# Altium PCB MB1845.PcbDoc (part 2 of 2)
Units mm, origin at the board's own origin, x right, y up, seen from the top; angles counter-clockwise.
Board outline 43.1 x 47.12 mm, 4 copper layers (Top Layer, Internal 1, Internal 2, Bottom Layer), stack 1.565 mm thick; 96 components, 86 nets, 349 pads, 596 vias.
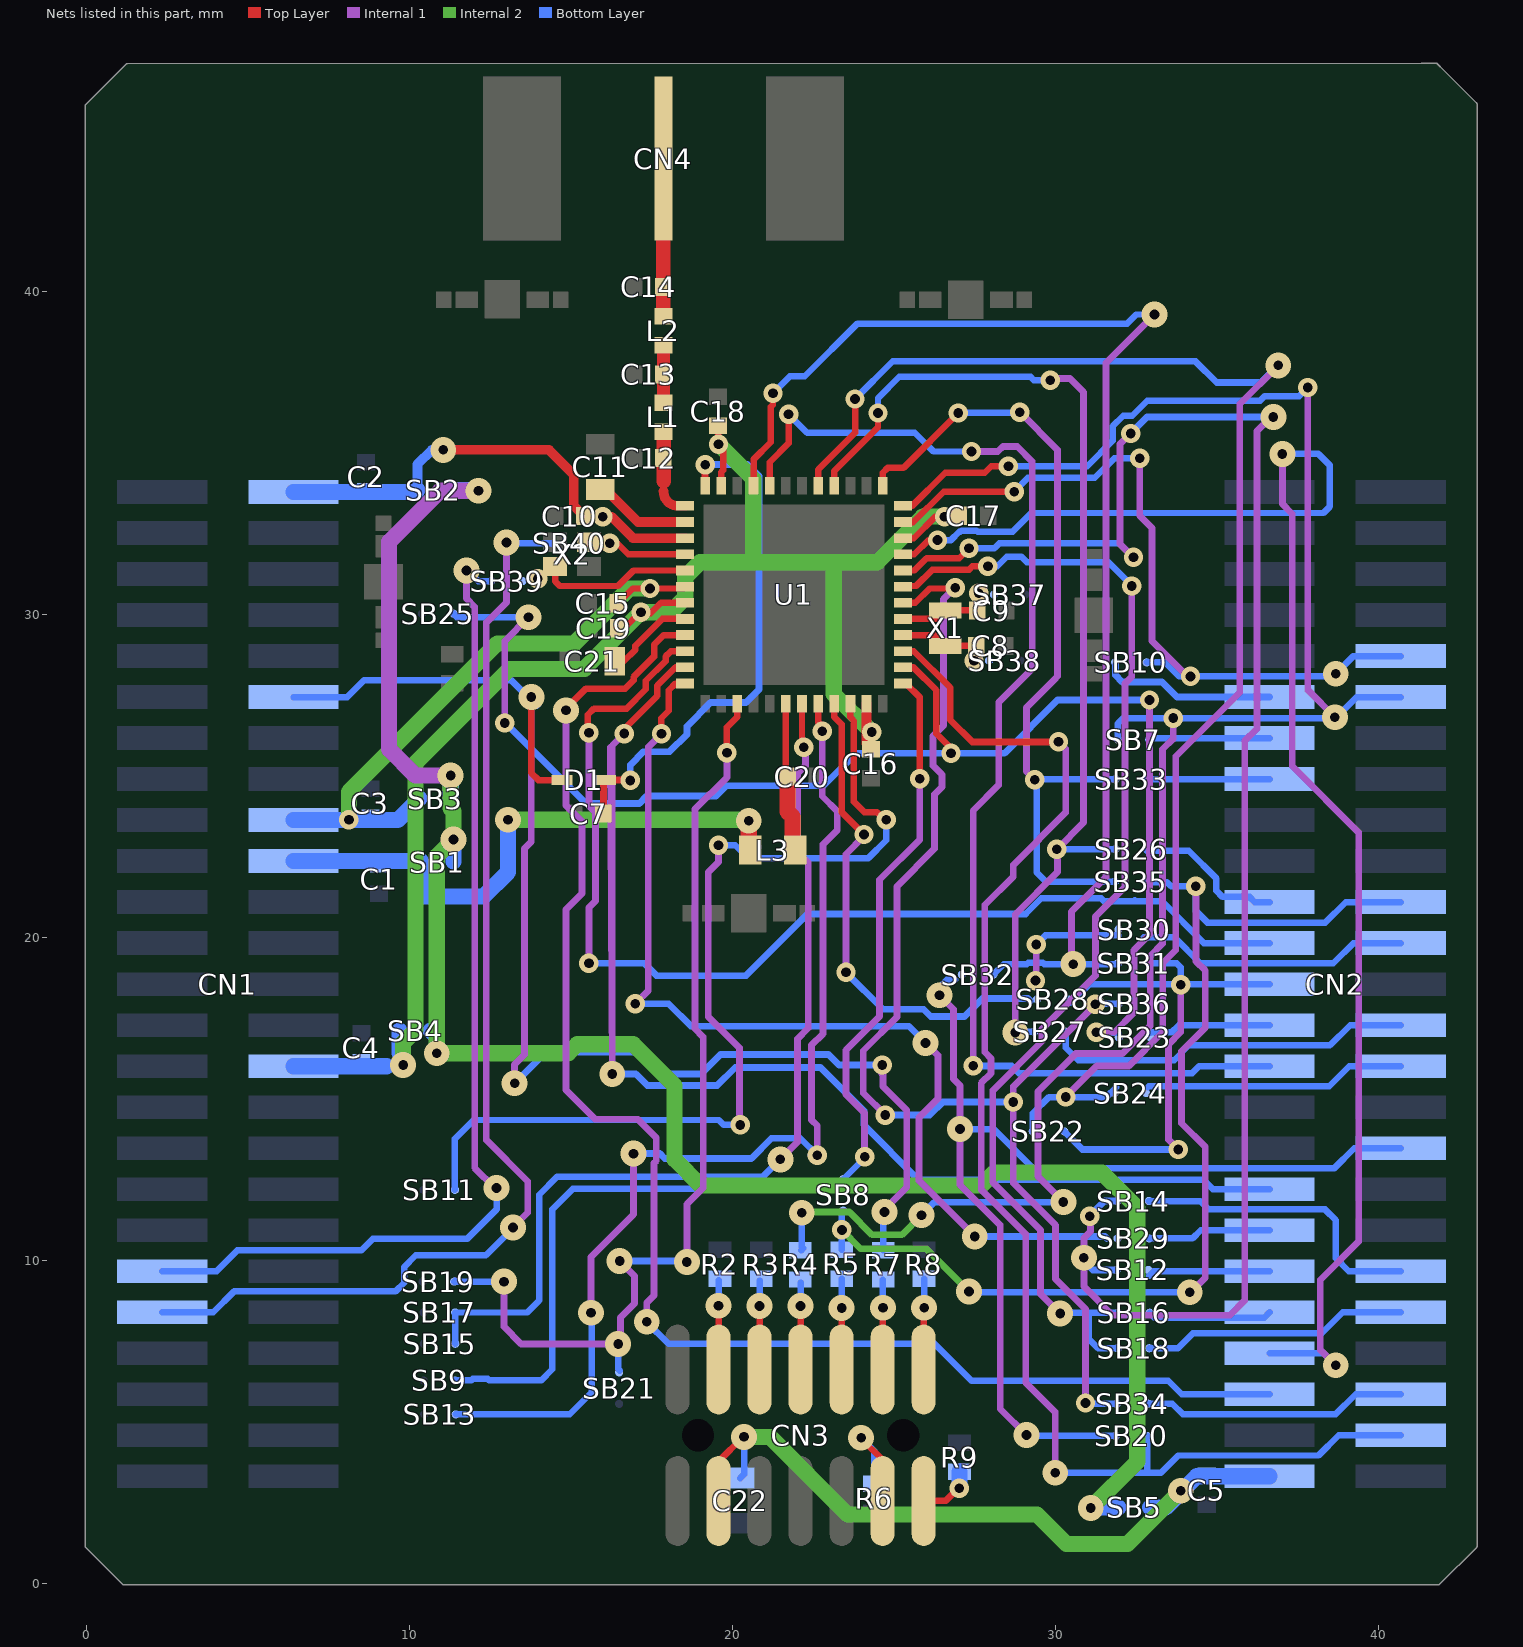
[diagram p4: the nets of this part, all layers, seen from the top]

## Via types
v1: diameter 0.6, hole 0.3, Top Layer to Bottom Layer, tented both sides, 513 vias
v2: diameter 0.8, hole 0.3, Top Layer to Bottom Layer, tented both sides, 83 vias

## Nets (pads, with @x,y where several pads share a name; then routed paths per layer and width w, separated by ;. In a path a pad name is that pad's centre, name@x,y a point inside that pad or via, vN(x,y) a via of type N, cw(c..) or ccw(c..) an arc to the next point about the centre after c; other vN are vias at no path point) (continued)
GPIO30: CN2.10 SB10.1 U1.23 | length 24.4
  Top Layer w0.2: U1.23@25.27,32.858 25.591,32.858 26.531,33.798 v1(28.715,33.798)
  Internal 1 w0.21: v1(32.601,34.835) 32.601,33.055 32.982,32.674 32.982,29.175 34.036,28.122 34.149,28.235 34.174,28.21 v1(34.174,28.077)
  Bottom Layer w0.2: v1(28.715,33.798) 29.143,34.225 31.21,34.225 31.82,34.835 v1(32.601,34.835) ; SB10.1@32.826,28.514 33.388,28.514 33.824,28.077 v1(34.174,28.077) ; 33.824,28.083 38.596,28.083 v2(38.672,28.159) 39.221,28.708 CN2.10@40.688,28.708
GPIO31: CN2.11 SB10.2 | length 5.4
  Bottom Layer w0.21: SB10.2@31.851,28.423 31.851,28.117 32.059,27.909 33.289,27.909 33.76,27.438 CN2.11@36.624,27.438
GPIO32: CN2.12 R4.2 SB7.1 U1.24 | length 62.3
  Top Layer w0.2: U1.24@25.27,33.358 25.553,33.358 26.581,34.386 27.804,34.386 28.004,34.585 v1(28.537,34.585)
  Internal 1 w0.21: v2(30.239,11.802) 29.452,12.589 29.452,15.227 30.624,16.399 32.068,16.399 32.931,17.263 32.931,19.422 33.312,19.803 33.312,25.822 33.643,26.153 v1(33.643,26.788) ; v1(37.808,37.024) 37.808,27.651 v2(38.646,26.813)
  Internal 2 w0.21: v2(22.136,11.471) 22.195,11.471 22.216,11.493 23.611,11.493 24.318,10.786 25.235,10.786 v2(25.845,11.395)
  Bottom Layer w0.2: R4.2@22.118,10.302 22.187,10.372 22.136,10.423 v2(22.136,11.471) ; v2(25.845,11.395) 26.251,11.802 v2(30.239,11.802) ; v1(28.537,34.585) 30.976,34.585 31.772,35.382 31.772,35.829 32.094,36.151 32.37,36.151 32.836,36.617 36.33,36.617 36.472,36.759 37.544,36.759 v1(37.808,37.024) ; SB7.1@31.922,26.2 31.922,26.617 32.093,26.788 v1(33.643,26.788) 38.672,26.788 39.323,27.438 CN2.12@40.688,27.438
GPIO33: CN2.13 SB7.2 | length 3.7
  Bottom Layer w0.2: SB7.2@32.897,26.2 32.929,26.168 CN2.13@36.624,26.168
GPIO34: CN2.15 SB33.1 | length 3.8
  Bottom Layer w0.2: SB33.1@32.844,24.832 32.91,24.898 CN2.15@36.624,24.898
GPIO37: CN2.21 SB26.1 | length 4.7
  Bottom Layer w0.2: SB26.1@32.824,22.679 34.119,22.679 34.977,21.821 34.977,21.44 35.167,21.25 36.005,21.25 36.167,21.088 CN2.21@36.624,21.088
GPIO38: CN2.22 R5.2 SB8.1 SB35.1 | length 35.3
  Internal 1 w0.21: v2(34.151,9.008) 34.176,9.008 34.633,9.465 34.633,13.505 33.897,14.242 33.897,16.47 34.633,17.207 34.633,18.964 34.343,19.255 v1(34.343,21.581)
  Internal 2 w0.21: v1(23.381,10.938) 23.965,10.354 25.997,10.354 v2(27.318,9.033)
  Bottom Layer w0.2: R5.2@23.376,10.328 23.376,11.402 ; v2(27.318,9.033) v2@27.343,9.008 ; SB35.1@32.829,21.708 33.448,21.708 33.575,21.581 v1(34.343,21.581) 34.343,20.813 34.701,20.454 38.351,20.454 38.985,21.088 CN2.22@40.688,21.088
  Bottom Layer w0.21: v2@27.343,9.008 v2(34.151,9.008)
GPIO39: CN2.23 U1.46 | length 34.8
  Top Layer w0.2: v1(15.547,26.33) 15.547,26.338 15.514,26.305 15.514,26.89 15.705,27.081 16.715,27.081 17.31,27.677 17.31,27.941 17.92,28.55 17.92,28.693 18.086,28.858 U1.46@18.52,28.858
  Internal 1 w0.21: v1@15.547,19.197 15.547,20.92 15.749,21.122 15.749,23.86 15.547,24.062 v1(15.547,26.33)
  Bottom Layer w0.2: 29.071,20.726 29.551,21.206 31.405,21.206 31.489,21.123 32.433,21.123 32.455,21.144 32.476,21.123 33.246,21.123 33.267,21.144 34.592,19.818 CN2.23@36.624,19.818
  Bottom Layer w0.21: v1(15.547,19.193) 17.262,19.193 17.643,18.812 20.409,18.812 22.314,20.717 29.071,20.717
GPIO40: CN2.24 SB30.2 | length 8.6
  Bottom Layer w0.2: 32.733,20.006 33.668,20.006 34.481,19.193 38.596,19.193 39.221,19.818 CN2.24@40.688,19.818
GPIO41: CN2.25 SB22.1 SB28.2 SB31.2 | length 17.1
  Internal 1 w0.21: v1(33.795,13.427) 33.49,13.732 33.49,16.678 33.871,17.059 v1(33.871,18.533)
  Bottom Layer w0.2: 30.472,17.974 31.047,18.548 v1@33.871,18.548 ; SB31.2@32.911,19.193 33.745,19.193 33.871,19.066 v1@33.871,18.548 ; CN2.25@36.624,18.548 v1@33.871,18.548
  Bottom Layer w0.21: SB22.1@30.266,13.988 30.827,13.427 v1(33.795,13.427)
GPIO42: CN2.27 SB23.2 SB36.2 | length 4.5
  Bottom Layer w0.2: 32.921,17.278 SB36.2@32.921,17.941 ; 32.93,17.044 32.921,17.053 33.585,17.053 33.811,17.278 CN2.27@36.624,17.278
GPIO43: CN2.28 SB27.1 | length 11.5
  Bottom Layer w0.2: SB27.1@30.31,17.075 30.31,16.582 30.696,16.196 33.668,16.196 34.125,16.653 38.494,16.653 39.119,17.278 CN2.28@40.688,17.278
GPIO44: CN2.29 U1.32 | length 39.6
  Top Layer w0.2: U1.32@21.145,33.983 21.145,34.711 21.73,35.297 v1(21.73,36.198)
  Internal 1 w0.21: v1(27.394,35.043) 28.207,35.043 28.366,35.201 28.81,35.201 29.274,34.738 29.274,28.313 28.237,27.276 28.237,24.709 27.445,23.917 v1(27.445,16.018)
  Bottom Layer w0.2: v1(21.73,36.198) 22.302,35.627 25.633,35.627 26.217,35.043 v1(27.394,35.043)
  Bottom Layer w0.21: v1(27.445,16.018) 28.639,16.018 28.867,15.789 34.227,15.789 34.446,16.008 CN2.29@36.624,16.008
GPIO45: CN2.30 SB24.1 | length 8.1
  Bottom Layer w0.2: 32.851,15.354 32.88,15.383 33.708,15.383 33.713,15.388 34.252,15.388 34.257,15.383 38.469,15.383 39.094,16.008 CN2.30@40.688,16.008
GPIO46: CN2.34 SB20.2 SB32.2 | length 32.9
  Internal 1 w0.21: v2(26.404,18.202) 26.835,17.771 26.835,15.612 27.039,15.408 v2(27.039,14.062) 27.039,12.334 28.283,11.089 28.283,5.401 v2(29.096,4.588)
  Internal 2 w0.21: v2(29.096,4.588) v2@29.147,4.588
  Bottom Layer w0.2: v2@26.412,18.21 v2(26.404,18.202) 26.404,18.456 26.632,18.685 26.894,18.685 ; v2@27.039,14.163 v2(27.039,14.062) 28.086,14.062 29.305,12.843 38.621,12.843 39.246,13.468 CN2.34@40.688,13.468 ; v2@29.096,4.557 SB20.2@31.858,4.557
GPIO47: CN2.35 U1.47 | length 46.4
  Top Layer w0.2: v1(16.644,26.308) 16.572,26.379 17.183,26.991 17.666,27.473 17.666,27.793 18.231,28.358 U1.47@18.52,28.358
  Internal 1 w0.21: 16.218,25.882 v2(16.269,15.764) 16.269,25.933 v1(16.644,26.308)
  Bottom Layer w0.2: 27.586,12.487 34.582,12.487 34.871,12.198 CN2.35@36.624,12.198
  Bottom Layer w0.21: v2(16.269,15.764) 16.999,15.764 17.355,15.408 19.519,15.408 20.078,15.967 22.721,15.967 24.061,14.626 24.061,14.184 25.758,12.487 27.586,12.487
GPIO49: CN2.37 SB29.2 | length 3.8
  Bottom Layer w0.2: SB29.2@32.891,10.674 34.236,10.674 34.49,10.928 CN2.37@36.624,10.928
GPIO50: CN2.39 SB12.2 | length 3.8
  Bottom Layer w0.2: 32.897,9.521 33.034,9.658 CN2.39@36.624,9.658
GPIO51: CN2.40 SB14.2 | length 9.4
  Bottom Layer w0.2: SB14.2@32.889,11.832 34.481,11.832 34.741,11.573 38.342,11.573 38.672,11.243 38.672,10.066 39.08,9.658 CN2.40@40.688,9.658
GPIO52: CN2.41 SB16.2 | length 3.8
  Bottom Layer w0.2: SB16.2@32.91,8.371 33.061,8.22 36.456,8.22 CN2.41@36.624,8.388
GPIO53: CN2.42 SB18.2 | length 8.3
  Bottom Layer w0.2: SB18.2@32.898,7.274 33.789,7.274 34.252,7.738 38.24,7.738 38.891,8.388 CN2.42@40.688,8.388
GPIO54: CN2.43 U1.21 | length 48.9
  Top Layer w0.2: U1.21@25.27,31.858 25.625,31.858 26.067,32.299 v1(26.342,32.299)
  Internal 1 w0.21: v2(37.021,34.966) 37.021,33.417 37.326,33.112 37.326,25.303 39.383,23.246 39.383,10.582 38.195,9.395 38.195,7.224 v2(38.672,6.747)
  Bottom Layer w0.2: v1(26.342,32.299) 26.759,32.299 27.013,32.553 27.048,32.553 27.09,32.595 27.546,32.595 27.588,32.553 28.664,32.553 29.248,33.138 38.291,33.138 38.494,33.341 38.494,34.611 38.138,34.966 v2(37.021,34.966) ; CN2.43@36.624,7.118 38.3,7.118 v2(38.672,6.747)
GPIO55: CN2.45 U1.45 | length 46.6
  Top Layer w0.2: v2(14.836,27.026) 14.836,27.081 15.456,27.702 16.675,27.702 16.929,27.956 16.929,28.058 17.564,28.693 17.564,29.056 17.867,29.358 U1.45@18.52,29.358
  Internal 1 w0.21: v2(14.836,27.026) 14.836,24.081 15.329,23.587 15.329,21.352 14.836,20.858 14.836,15.267 15.736,14.367 17.056,14.367 17.634,13.79 17.634,13.078 17.565,13.01 17.565,8.909 17.336,8.68 v2(17.336,8.093)
  Bottom Layer w0.2: 30.137,6.264 33.49,6.264 33.906,5.848 CN2.45@36.624,5.848
  Bottom Layer w0.21: v2(17.336,8.093) 18.016,7.413 26.253,7.413 27.402,6.264 30.137,6.264
GPIO56: CN2.46 SB34.2 | length 8.2
  Bottom Layer w0.2: SB34.2@32.865,5.556 33.611,5.556 33.941,5.226 38.667,5.226 39.289,5.848 CN2.46@40.688,5.848
GPIO57: CN2.48 SB20.1 U1.15 | length 43.8
  Top Layer w0.2: U1.15@25.27,28.858 25.609,28.858 26.734,27.733 26.734,27.189
  Top Layer w0.21: 26.734,27.189 26.734,26.737 27.42,26.051 v1(30.087,26.051)
  Internal 1 w0.21: v2@29.858,3.42 v2(29.985,3.42) 29.985,5.299 29.071,6.214 29.071,10.811 27.694,12.188 27.694,15.482 28,15.788 28,16.248 27.805,16.443 27.805,21.001 28.69,21.885 28.69,22.241 30.31,23.861 30.31,25.828 v1(30.087,26.051)
  Bottom Layer w0.2: v2(29.985,3.42) 33.262,3.42 33.795,3.953 38.138,3.953 38.764,4.578 CN2.48@40.688,4.578 ; 32.833,3.547 SB20.1@32.833,4.557
NetC7_2: C7.2 D1.1 U1.36 | length 16.5
  Top Layer w0.21: C7.2@15.997,23.83 15.997,24.807 D1.1@16.059,24.869 v1@16.816,24.869 ; U1.36@19.145,33.983 v1(19.145,34.636)
  Bottom Layer w0.21: v1(16.828,24.857) 16.828,25.34 17.234,25.746 18.047,25.746 18.58,26.28 18.58,26.534 19.317,27.27 20.409,27.27 20.816,27.677 20.816,34.281 20.46,34.636 v1(19.145,34.636)
NetC8_2: C8.2 SB38.1 U1.16 X1.2 | length 2.3
  Top Layer w0.2: U1.16@25.27,29.358 26.246,29.358 X1.2@26.581,29.022 27.406,29.022 C8.2@27.445,29.062
  other v1: 27.47,28.566
NetC9_2: C9.2 SB37.1 U1.17 X1.1 | length 2.3
  Top Layer w0.2: U1.17@25.27,29.858 26.317,29.858 X1.1@26.581,30.122 27.449,30.122 C9.2@27.453,30.119
  other v1: 27.623,30.648
NetC11_2: C11.2 U1.38 | length 2.9
  Top Layer w0.3: C11.2@16.057,33.866 17.064,32.858 U1.38@18.52,32.858
NetC12_2: C12.2 L1.1 U1.37 | length 2.6
  Top Layer w0.3: 17.856,33.811 ccw(c18.309,33.811) 18.309,33.358 U1.37@18.52,33.358
  Top Layer w0.4: L1.1@17.819,35.606 17.91,35.606 17.91,35.54 L1.1@17.859,35.54 ; C12.2@17.823,34.852 C12.2@17.856,34.885
  Top Layer w0.45: 17.859,34.116 17.859,34.844 L1.1@17.859,35.54
NetC13_2: C13.2 L1.2 L2.1 | length 1.8
  Top Layer w0.4: L1.2@17.805,36.569 L1.2@17.819,36.556 ; L1.2@17.854,36.556 C13.2@17.854,37.43 L2.1@17.854,38.335
NetC14_2: C14.2 CN4.1 L2.2 | length 4.7
  Top Layer w0.45: L2.2@17.854,39.236 C14.2@17.854,40.142 CN4.1@17.854,43.891
NetC20_2: C20.2 L3.2 U1.6 | length 4.6
  Top Layer w0.2: C20.2@21.645,25.004 U1.6@21.645,27.233
  Top Layer w0.5: C20.2@21.697,24.972 21.697,23.892 21.847,23.741 21.847,22.79 L3.2@21.941,22.697
NetC21_2: C21.2 U1.44 | length 2.8
  Top Layer w0.2: C21.2@16.349,28.545 16.63,28.545 16.98,28.896 16.98,29.022 17.817,29.858 U1.44@18.52,29.858
NetCN3_4: CN3.4 R2.1 | length 2.8
  Top Layer w0.2: CN3.4@19.561,6.614 v2(19.561,8.589) v2@19.561,8.639
  Bottom Layer w0.2: v2(19.561,8.589) R2.1@19.561,9.384
NetCN3_6: CN3.6 R3.1 | length 2.8
  Top Layer w0.2: CN3.6@20.831,6.614 v2(20.831,8.579)
  Bottom Layer w0.2: v2(20.831,8.579) R3.1@20.831,9.372
NetCN3_8: CN3.8 R4.1 | length 2.7
  Top Layer w0.2: CN3.8@22.101,6.614 v2(22.101,8.579)
  Bottom Layer w0.2: v2(22.101,8.579) R4.1@22.101,9.31
NetCN3_10: CN3.10 R5.1 | length 2.8
  Top Layer w0.2: CN3.10@23.371,6.614 v2(23.371,8.519)
  Bottom Layer w0.2: v2(23.371,8.519) R5.1@23.371,9.423
NetCN3_11: CN3.11 R6.2 | length 3.9
  Top Layer w0.2: v2(23.976,4.504) 23.951,4.504 24.641,3.814 CN3.11@24.641,2.544
  Bottom Layer w0.2: v2(23.976,4.504) 24.386,4.094 R6.2@24.386,3.081
NetCN3_12: CN3.12 R7.1 | length 2.8
  Top Layer w0.2: CN3.12@24.641,6.614 24.641,8.519 v2(24.651,8.529)
  Bottom Layer w0.2: v2(24.651,8.529) R7.1@24.651,9.396
NetCN3_13: CN3.13 R9.2 | length 1.6
  Top Layer w0.2: CN3.13@25.911,2.544 26.591,2.544 v1@26.901,2.854
  Bottom Layer w0.5: v1@27.024,2.947 R9.2@27.024,3.45
  other v1: 27.013,2.937
NetCN3_14: CN3.14 R8.1 | length 2.8
  Top Layer w0.2: CN3.14@25.911,6.614 25.911,8.539 25.921,8.529 v2(25.926,8.529)
  Bottom Layer w0.2: v2(25.926,8.529) R8.1@25.926,9.424
NetSB1_1: SB1.1 SB2.1 SB3.1 SB4.1 SB5.1 | length 60.4
  Internal 1 w0.5: v2(11.265,25.01) 10.173,25.01 9.36,25.822 9.36,32.249 10.941,33.829 v2(12.129,33.829)
  Internal 2 w0.5: v2(11.265,25.01) 11.265,23.994 11.355,23.904 v2(11.355,23.028) 10.833,22.507 v2(10.833,16.41) 14.909,16.41 15.187,16.688 16.92,16.688 18.199,15.408 18.199,13.122 19.012,12.31 27.699,12.31 28.105,12.716 31.433,12.716 32.525,11.624 32.525,3.765 v2(31.087,2.327)
  Bottom Layer w0.5: SB4.1@10.651,17.107 10.84,16.918 10.84,16.41 v2(10.833,16.41) ; SB2.1@11.214,33.846 12.101,33.846 12.123,33.823 v2(12.129,33.829) ; v2(11.265,25.01) 11.269,25.006 SB3.1@11.269,24.295 ; SB1.1@11.355,22.342 v2(11.355,23.028) ; v2(31.087,2.327) 31.103,2.343 SB5.1@31.947,2.343
NetSB8_2: SB8.2 SB9.2 U1.13 | length 34.7
  Top Layer w0.21: U1.13@25.27,27.858 25.359,27.858 25.794,27.423 v1(25.794,24.908)
  Internal 1 w0.21: v1(24.085,13.205) 24.085,14.552 23.508,15.129 23.508,16.504 24.549,17.546 24.549,21.781 25.794,23.026 v1(25.794,24.908)
  Bottom Layer w0.2: SB9.2@11.4,6.277 11.897,6.277 11.952,6.332 12.407,6.332 12.462,6.277 14.067,6.277 14.415,6.625 14.415,11.573 15.05,12.208 23.12,12.208 SB8.2@23.421,12.509 24.118,13.205 v1(24.085,13.205)
NetSB11_2: SB11.2 U1.10 | length 30.8
  Top Layer w0.2: U1.10@23.645,27.233 23.645,26.816 23.721,26.739 23.721,26.731 23.745,26.707 23.745,24.595 23.751,24.589 23.751,24.561 23.753,24.559 23.753,24.2 24.075,23.878 24.462,23.878 24.702,23.638 v1(24.753,23.638)
  Internal 1 w0.21: v1(19.561,22.851) 19.561,22.333 19.241,22.012 19.241,17.542 20.206,16.577 v1@20.206,14.113 ; v1@20.13,14.037 v1@20.206,14.113 ; v1(20.231,14.189) 20.231,14.138 v1@20.206,14.113
  Bottom Layer w0.2: SB11.2@11.399,12.177 11.399,13.764 11.976,14.342 19.571,14.342 19.723,14.189 v1(20.231,14.189) ; v1@19.52,22.851 v1(19.561,22.851) 20.076,22.851 20.473,22.454 24.203,22.454 24.753,23.003 v1(24.753,23.638)
NetSB12_1: SB12.1 SB14.1 U1.20 | length 54.3
  Top Layer w0.2: U1.20@25.27,31.358 25.621,31.358 26.003,31.741 27.013,31.741 v1(27.318,32.045)
  Internal 1 w0.21: v1(31.052,11.365) 31.077,11.339 31.077,10.887 30.874,10.684 v2(30.874,10.074) 30.874,9.185 31.763,8.296 35.395,8.296 35.852,8.754 35.852,26.076 36.233,26.457 36.233,35.678 36.665,36.109 v2(36.741,36.109) ; v1(32.322,35.601) 31.992,35.271 31.992,32.185 v1(32.41,31.766)
  Bottom Layer w0.2: v1(27.318,32.045) 28.105,32.045 28.258,32.198 31.954,32.198 32.385,31.766 v1(32.41,31.766)
  Bottom Layer w0.21: v2(30.874,10.074) 30.874,9.973 31.149,9.698 SB12.1@31.897,9.698 ; v1(31.052,11.365) 31.047,11.37 31.509,11.832 SB14.1@31.914,11.832 ; v1(32.322,35.601) 32.83,36.109 v2(36.741,36.109)
NetSB13_2: SB13.2 U1.8 | length 33.7
  Top Layer w0.2: U1.8@22.645,27.233 22.645,26.665 v1@22.79,26.52
  Internal 1 w0.21: v2(15.609,8.373) 15.609,10.1 16.929,11.421 v2(16.929,13.3) ; v1(22.619,13.249) 22.619,14.164 22.441,14.342 22.441,16.66 22.791,17.01 22.791,22.878 23.24,23.326 23.24,23.898 22.771,24.367 v1(22.771,26.381)
  Bottom Layer w0.2: SB13.2@11.423,5.226 14.952,5.226 15.634,5.909 15.634,8.296 v2@15.71,8.373
  Bottom Layer w0.21: v2@16.802,13.554 16.955,13.402 16.929,13.376 v2(16.929,13.3) 17.742,13.3 17.895,13.148 20.575,13.148 21.205,13.777 22.091,13.777 v1(22.619,13.249) v1@22.416,13.249
NetSB15_2: SB15.2 SB17.2 U1.7 | length 29.8
  Top Layer w0.2: U1.7@22.145,27.233 22.145,25.938 v1(22.197,25.885)
  Internal 1 w0.21: v2(21.476,13.122) 22.009,13.656 22.009,16.856 22.34,17.186 22.34,22.317 22.009,22.647 22.009,25.074 22.25,25.314 v1@22.25,25.885 ; v1(22.197,25.885) v1@22.25,25.885 ; v1@22.305,25.94 v1@22.25,25.885
  Bottom Layer w0.2: SB15.2@11.403,7.42 SB17.2@11.403,8.381 13.635,8.381 14.008,8.754 14.008,12.03 14.567,12.589 20.938,12.589 v2@21.474,13.125
NetSB16_1: SB16.1 SB18.1 U1.19 | length 36.5
  Top Layer w0.2: U1.19@25.27,30.858 25.29,30.878 25.678,30.878 26.185,31.385 27.318,31.385 27.42,31.487 v1(27.902,31.487)
  Internal 1 w0.21: v2(30.137,8.347) 29.528,8.957 29.528,10.938 28.054,12.412 28.054,15.256 29.579,16.781 29.579,17.161 31.23,18.812 31.23,20.641 32.144,21.555 32.144,27.854 32.359,28.069 v1(32.359,30.877)
  Internal 2 w0.21: v2@30.087,8.398 v2(30.137,8.347)
  Bottom Layer w0.2: v1(27.902,31.487) 28.191,31.487 28.487,31.783 28.943,31.783 29.112,31.614 31.636,31.614 32.373,30.877 v1@32.398,30.877 ; v2@30.417,8.371 31.026,8.371 ; SB18.1@31.923,7.274 31.312,7.274 31.026,7.56 31.026,8.371 ; SB16.1@31.935,8.371 31.026,8.371
NetSB19_2: SB19.2 SB21.2 U1.3 | length 30.8
  Top Layer w0.2: v1(19.82,25.712) 19.82,26.503 20.145,26.828 U1.3@20.145,27.233
  Internal 1 w0.21: v2(12.916,9.338) 12.916,7.941 13.45,7.407 v2(16.452,7.407) 16.523,7.407 16.523,8.225 16.959,8.661 16.959,9.511 v2(16.498,9.973) ; v2(18.58,9.947) 18.58,11.736 19.085,12.24 19.085,16.918 18.834,17.168 18.834,23.968 19.82,24.954 v1(19.82,25.712)
  Bottom Layer w0.2: SB19.2@11.375,9.337 11.402,9.363 11.427,9.338 v2(12.916,9.338) ; v2(16.452,7.407) 16.452,6.632 SB21.2@16.506,6.578
  Bottom Layer w0.21: v2(16.498,9.973) 18.555,9.973 v2(18.58,9.947)
NetSB22_2: SB22.2 SB24.2 U1.29 | length 46.7
  Top Layer w0.2: U1.29@22.645,33.983 22.645,34.484 23.787,35.627 v1(23.787,36.668)
  Internal 1 w0.21: v1(30.31,15.053) 31.27,16.014 32.267,16.014 33.316,17.063 33.316,19.197 33.719,19.599 33.719,25.594 35.7,27.575 35.7,36.516 v2(36.894,37.71)
  Bottom Layer w0.2: v1(23.787,36.668) 24.955,37.836 ; SB22.2@29.291,13.988 29.291,14.549 29.794,15.053 v1(30.31,15.053) 31.574,15.053 31.876,15.354
  Bottom Layer w0.21: 24.955,37.836 34.329,37.836 34.989,37.176 36.36,37.176 v2(36.894,37.71)
NetSB23_1: SB23.1 SB25.1 U1.14 | length 43.8
  Top Layer w0.21: U1.14@25.27,28.358 25.595,28.358 26.302,27.651 26.302,26.305 26.785,25.822 26.785,25.695 v1(26.759,25.695)
  Internal 1 w0.21: v1(12.942,26.635) 12.942,29.175 v2(13.678,29.912) ; v1(31.255,17.059) 31.814,17.059 32.423,17.669 32.423,19.599 32.906,20.082 v1(32.906,27.346)
  Bottom Layer w0.2: v1(31.255,17.059) 31.275,17.059 31.29,17.044 31.955,17.044
  Bottom Layer w0.21: SB25.1@11.352,30.022 11.462,29.912 v2(13.678,29.912) ; v1(12.942,26.635) 12.967,26.635 15.456,24.146 17.108,24.146 17.337,24.375 19.486,24.375 19.805,24.693 22.81,24.693 23.813,25.695 v1(26.759,25.695) 28.41,25.695 30.061,27.346 v1(32.906,27.346)
NetSB26_2: SB26.2 SB27.2 U1.28 | length 33.1
  Top Layer w0.2: U1.28@23.145,33.983 23.145,34.438 24.499,35.792 v1(24.499,36.236)
  Internal 1 w0.21: v2(28.749,17.053) 28.749,20.706 30.061,22.018 v1@30.061,22.495 ; v1(29.833,37.252) 29.833,37.151 29.985,37.303 30.442,37.303 30.866,36.879 30.866,23.554 v1(30.036,22.724)
  Bottom Layer w0.2: v1(24.499,36.236) 24.499,36.694 25.159,37.354 29.223,37.354 29.325,37.252 v1(29.833,37.252) ; v2(28.749,17.053) 28.772,17.075 SB27.2@29.335,17.075 ; v1@30.087,22.731 SB26.2@31.858,22.731
NetSB28_1: SB28.1 SB30.1 U1.9 | length 19.3
  Top Layer w0.2: U1.9@23.145,27.233 23.145,26.821 23.371,26.594 23.371,23.876 v1(24.067,23.181)
  Internal 1 w0.21: v1(23.508,18.914) 23.508,22.571 24.067,23.13 v1(24.067,23.181) ; v1(29.377,18.66) 29.401,18.683 v1(29.401,19.777)
  Bottom Layer w0.21: v1(23.508,18.914) 24.651,17.771 25.909,17.771 26.132,17.547 27.177,17.547 27.731,18.101 29.147,18.101 29.223,18.025 ; v1(29.401,19.777) 29.685,20.061 31.943,20.061
NetSB29_1: SB29.1 U1.48 | length 31.4
  Top Layer w0.2: v1(17.793,26.305) 17.79,26.308 17.79,26.784 18.022,27.016 18.022,27.651 18.229,27.858 U1.48@18.52,27.858
  Internal 1 w0.21: v1(16.98,17.941) 17.387,18.347 17.387,25.899 v1(17.793,26.305) ; v2(25.972,16.725) 26.353,16.344 26.353,15.002 25.769,14.418 25.769,12.462 v2(27.496,10.735)
  Bottom Layer w0.21: v1(16.98,17.941) 18.015,17.941 18.709,17.247 25.45,17.247 v2(25.972,16.725) ; v2(27.496,10.735) 31.53,10.735 31.591,10.674
NetSB31_1: SB31.1 SB32.1 U1.33 | length 41.7
  Top Layer w0.2: U1.33@20.645,33.983 20.645,34.796 21.18,35.331 21.18,36.426 21.247,36.494 v1(21.247,36.846)
  Internal 1 w0.21: v2(30.544,19.168) 30.544,18.939 30.493,18.888 30.493,20.793 31.56,21.86 31.56,37.786 v2(33.058,39.284)
  Bottom Layer w0.2: v1(21.247,36.846) 21.772,37.371 22.229,37.371 23.864,39.005 32.22,39.005 32.5,39.284 v2(33.058,39.284) ; SB32.1@28.069,18.845 28.392,19.168 29.107,19.168 29.149,19.21 29.605,19.21 29.647,19.168 v2(30.544,19.168) SB31.1@31.939,19.168
NetSB33_2: SB33.2 SB35.2 U1.25 | length 25.8
  Top Layer w0.2: U1.25@24.645,33.983 24.645,34.386 24.793,34.535 25.286,34.535 v1(26.988,36.236)
  Internal 1 w0.21: v1(28.893,36.262) 30.061,35.093 30.061,28.083 30.015,28.037 ; v1(29.35,24.883) 29.096,25.137 29.096,27.117 30.015,28.035
  Bottom Layer w0.2: v1(26.988,36.236) v1@28.918,36.236 ; SB35.2@31.842,21.723 29.699,21.723 29.41,22.012 29.41,24.833 29.35,24.893 SB33.2@31.852,24.893
NetSB34_1: SB34.1 SB36.1 U1.18 | length 40.1
  Top Layer w0.2: U1.18@25.27,30.358 25.656,30.358 26.099,30.801 26.708,30.801 26.861,30.953 26.886,30.928 v1(26.886,30.826)
  Internal 1 w0.21: v1(24.727,14.494) 24.041,15.18 24.041,16.486 25.083,17.528 25.083,21.576 26.251,22.744 26.251,24.428 26.48,24.656 26.48,25.035 26.2,25.314 26.2,26.229 26.531,26.559 26.531,30.471 v1(26.886,30.826) ; v1(30.925,5.579) 30.925,8.486 29.992,9.419 29.992,11.084 28.69,12.386 v1(28.69,14.9) 28.69,15.383 v1(31.23,17.923)
  Bottom Layer w0.2: v1@30.95,5.556 SB34.1@31.89,5.556 ; v1(31.23,17.923) 31.248,17.941 SB36.1@31.946,17.941
  Bottom Layer w0.21: v1(24.727,14.494) 26.099,14.494 26.505,14.9 v1(28.69,14.9)
NetSB39_1: SB39.1 U1.41 X2.1 | length 4.7
  Top Layer w0.2: X2.1@14.501,31.48 14.501,31.02 14.642,30.878 16.447,30.878 16.927,31.358 U1.41@18.52,31.358
  other v1: 13.958,31.099
NetSB40_1: SB40.1 U1.40 X2.3 | length 3.2
  Top Layer w0.2: v1(16.193,32.198) 16.421,32.198 16.761,31.858 U1.40@18.52,31.858
  Bottom Layer w0.2: SB40.1@15.424,32.198 v1(16.193,32.198)
NRST: CN1.12 D1.2 R7.2 | length 42.8
  Top Layer w0.2: v2(13.764,27.438) 13.764,25.088 13.983,24.869 D1.2@14.709,24.869
  Internal 1 w0.21: v2(13.246,15.478) 13.246,16.059 13.551,16.364 13.551,22.749 13.764,22.962 v2(13.764,27.438) ; v1(24.626,16.043) 24.626,15.769 24.651,15.743 24.651,15.383 25.392,14.642 25.392,12.263 24.702,11.573 v2(24.702,11.493)
  Bottom Layer w0.2: CN1.12@6.398,27.438 8.061,27.438 8.587,27.964 13.137,27.964 13.932,27.169 13.983,27.219 v2(13.764,27.438) ; R7.2@24.658,10.303 v2@24.658,11.479
  Bottom Layer w0.21: v2(13.246,15.478) 14.218,16.45 17.082,16.45 17.763,15.768 19.017,15.768 19.622,16.374 22.962,16.374 23.292,16.043 v1(24.626,16.043)
OSC_IN: CN1.39 SB39.2 | length 32.3
  Internal 1 w0.21: v2(11.753,31.36) 11.753,30.49 12.01,30.234 12.01,12.86 12.637,12.233 v2(12.688,12.233)
  Bottom Layer w0.2: CN1.39@2.334,9.658 4.017,9.658 4.661,10.302 8.496,10.302 8.852,10.659 11.773,10.659 12.688,11.573 v2(12.688,12.233) ; v2(11.753,31.36) 11.773,31.379 12.123,31.029 SB39.2@12.518,31.029
OSC_OUT: CN1.41 SB40.2 | length 35.9
  Internal 1 w0.21: v2@12.992,32.299 v2(12.992,32.223) 12.992,30.369 12.37,29.747 12.37,13.719 13.653,12.437 13.653,11.471 v2(13.196,11.014)
  Bottom Layer w0.2: CN1.41@2.334,8.388 3.915,8.388 4.56,9.033 9.557,9.033 9.825,9.301 9.825,9.79 10.186,10.151 12.357,10.151 13.221,11.014 v2(13.196,11.014) ; v2@13.069,32.198 SB40.2@14.449,32.198
VDD1: C2.2 C10.1 CN1.2 SB2.2 U1.39 | length 14.9
  Top Layer w0.3: v2@11.011,35.093 v2(11.037,35.093) 14.313,35.093 15.077,34.33 15.077,33.369 C10.1@15.401,33.045 15.419,33.026 v1(15.971,33.026) 16.244,33.026 16.912,32.358 U1.39@18.52,32.358
  Bottom Layer w0.3: SB2.2@10.239,33.846 10.239,34.651 10.681,35.093 v2(11.037,35.093)
  Bottom Layer w0.5: CN1.2@6.398,33.788 10.181,33.788 SB2.2@10.239,33.846
VDD3: C3.2 C15.1 CN1.18 SB3.2 U1.42 | length 19.3
  Top Layer w0.2: C15.1@16.446,30.342 16.905,30.801 v1(17.437,30.801) 18.463,30.801 U1.42@18.52,30.858
  Internal 2 w0.5: v1(8.116,23.638) 8.116,24.502 12.713,29.099 15.101,29.099 16.802,30.801 v1(17.437,30.801)
  Bottom Layer w0.5: CN1.18@6.398,23.628 9.627,23.628 SB3.2@10.294,24.295
VDD4: C4.2 C16.1 C17.1 C18.1 C19.1 CN1.30 SB4.2 U1.11 U1.22 U1.35 U1.43 | length 49.7
  Top Layer w0.2: C19.1@16.453,29.556 16.625,29.556 17.107,30.039 17.463,30.039 17.782,30.358 U1.43@18.52,30.358 ; v1@19.546,35.287 C18.1@19.546,35.837 ; v1(19.561,35.271) 19.708,35.125 19.708,34.468 19.645,34.405 U1.35@19.645,33.983 ; U1.22@25.27,32.358 25.608,32.358 v1@26.277,33.026
  Top Layer w0.3: C16.1@24.145,25.999 U1.11@24.145,27.233
  Internal 2 w0.5: v2(9.795,16.046) 9.795,16.735 10.173,17.113 10.173,25.391 13.094,28.312 15.405,28.312 v1(17.158,30.064) 18.072,30.064 18.53,30.521 18.53,31.156 18.987,31.614 20.638,31.614 ; v1(19.561,35.271) 20.638,34.195 20.638,31.614 ; v1(24.303,26.356) 23.127,27.532 23.127,31.614 ; v1(26.556,33.026) 25.886,33.026 24.473,31.614 23.127,31.614 ; 20.638,31.614 23.127,31.614
  Bottom Layer w0.5: CN1.30@6.398,16.008 9.274,16.008 ; v2@9.676,16.41 SB4.2@9.676,17.107
VDD15: C5.2 C22.2 CN2.49 CN3.3 SB5.2 | length 23.3
  Top Layer w0.2: CN3.3@19.561,2.544 19.561,3.764 20.326,4.529 v2(20.351,4.529)
  Internal 2 w0.5: v2(20.351,4.529) 21.154,4.529 23.559,2.124 29.426,2.124 30.341,1.21 32.22,1.21 v2(33.871,2.861)
  Bottom Layer w0.2: C22.2@20.231,3.254 20.351,3.375 v2(20.351,4.529)
  Bottom Layer w0.5: SB5.2@32.922,2.343 33.404,2.343 34.37,3.308 CN2.49@36.624,3.308
VDDA: C1.2 CN1.20 L3.1 SB1.2 | length 18.2
  Top Layer w0.5: v2(20.496,23.609) 20.496,22.742 L3.1@20.541,22.697 L3.1@20.644,22.801
  Internal 2 w0.5: v2(13.043,23.638) 20.46,23.638 20.485,23.663 v2@20.46,23.663
  Bottom Layer w0.5: CN1.20@6.398,22.358 10.339,22.358 SB1.2@10.368,22.329 10.368,21.259 12.28,21.259 13.043,22.022 v2(13.043,23.638)
pads on no net: CN1.3 CN1.4 CN1.5 CN1.10 CN1.11 CN1.16 CN1.19 CN1.21 CN1.23 CN1.27 CN1.32 CN1.43 CN1.48 CN1.50 CN2.1 CN2.3 CN2.4 CN2.5 CN2.6 CN2.16 CN2.17 CN2.18 CN2.19 CN2.31 CN2.33 CN2.36 CN2.47 CN3.1 CN3.2 CN3.9 CN3.NPTH1 CN3.NPTH2 Designator15.1
copper on no net:
  other v1: 10.833,12.995

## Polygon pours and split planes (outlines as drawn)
GND on Top Layer "Top Layer-GND" (solid, remove dead copper, pour order 9): -6.693,52.045 44.006,52.045 44.006,-1.076 -6.693,-1.076
NetC12_2 on Top Layer "RF_OUT" (solid, pour order 5): 18.086,34.103 18.004,33.83 17.707,33.82 17.641,34.077
GND on Internal 1 "Internal 1-GND" (solid, remove dead copper, pour order 13): -2.679,46.584 15.659,46.584 15.659,31.944 19.876,31.944 19.876,46.584 44.793,46.584 44.793,-1.635 -2.679,-1.635
GND on Internal 2 "Internal 2-GND" (solid, remove dead copper, pour order 11): -4.508,46.634 47.486,46.634 47.486,-0.721 -4.508,-0.721
GND on Bottom Layer "Bottom Layer-GND" (solid, remove dead copper, pour order 7): -3.848,46.634 43.676,46.634 43.676,-1.508 -3.848,-1.508

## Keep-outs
Top Layer:
  rectangle: 17.641,36.045 18.086,36.158
Keep-Out Layer:
  lines w0.1: 43,1.141 43,45.795 41.78,47.015 1.26,47.015 0,45.755 0,1.139 1.139,0 41.852,0 42.504,0.647 43.001,1.141

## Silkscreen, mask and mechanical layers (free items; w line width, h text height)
Top Overlay:
  lines w0.05: -0.592,0 1.139,0 ; 0,-0.5 0,1.139
  lines w0.1: 18.204,35.128 18.795,37.008 ; 9.182,20.742 31.182,20.742 31.182,39.742 9.182,39.742 9.182,20.742
  text "L" at 1.245,41.838 h7.62
  text "MB1845A" at 2.769,1.988 h2.5
Bottom Overlay:
  lines w0.2: 33.246,18.025 33.897,18.025 ; 33.262,16.983 33.846,16.983
  text "H" at 40.962,42.376 h7.62
  text "C" at 35.288,41.106 h7.62
  text "I" at 40.505,38.176 h7.62
Top Solder:
  lines w1: 9.182,28.058 9.182,20.742 17.615,20.742 ; 9.182,33.925 9.182,39.742 9.944,39.742 ; 19.816,39.732 24.219,39.767 ; 23.371,20.742 31.153,20.742 31.153,26.813 ; 30.137,39.792 31.153,39.792 31.153,33.026
M1-Board Shape:
  lines w0.1: 43,1.141 43,45.795 ; 43.001,1.141 41.852,0 1.139,0 0,1.139 0,45.75 0,45.755 1.245,47 41.326,47.015 41.78,47.015 41.987,46.809 43,45.795 ; 43.001,45.795 43,45.795
M2-Board Dimensions:
  lines w0.1: -5.613,47 0.61,47 ; -5.334,0 0.889,0 ; 0,-11.198 0,0.464 ; 43,-10.994 43,0.667
  lines w0.254: -5.798,2 -5.131,0 ; -5.797,45 -5.131,47 ; -5.385,0 -4.877,0 ; -5.385,47 -4.877,47 ; -5.131,19.955 -5.131,0 ; -5.131,27.045 -5.131,47 ; -4.464,2 -5.131,0 ; -4.464,45 -5.131,47 ; 0,-11.121 0,-10.613 ; 2,-11.534 0,-10.867 ; 2,-10.201 0,-10.867 ; 17.955,-10.867 0,-10.867 ; 25.045,-10.867 43,-10.867 ; 41,-11.534 43,-10.867 ; 41,-10.201 43,-10.867 ; 43,-11.121 43,-10.613
  text "47 (mm)" at -4.29,20.209 h2 r90
  text "43 (mm)" at 18.209,-11.708 h2
M4-Bottom Dimensions:
  lines w0.1: -1.323,33.788 2.334,33.788 ; 2.334,-5 2.334,33.788 ; 36.624,-5 36.624,33.788 ; 44.448,33.788 2.334,33.788
  lines w0.254: 2.334,-5.254 2.334,-4.746 ; 4.334,-5.667 2.334,-5 ; 4.334,-4.333 2.334,-5 ; 14.717,-5 2.334,-5 ; 24.242,-5 36.624,-5 ; 34.624,-5.667 36.624,-5 ; 34.624,-4.333 36.624,-5 ; 36.624,-5.254 36.624,-4.746
  text "34.29 (mm)" at 14.971,-5.841 h2
  text "CN1/CN2 spacing" at 12.954,-7.595 h2
Drill Drawing:
  drawing of 315 lines, arcs and shapes, not listed
  text "mils" at 31.397,176.353 h2.54
  text "mils" at 19.916,176.302 h2.54
  text "Layer" at -0.699,115.405 h1.52
  text "Name" at 9.713,115.405 h1.52
  text "Material" at 33.329,115.405 h1.52
  text "Thickness" at 55.167,115.405 h1.52
  text "Constant" at 71.673,115.405 h1.52
  text "Board Layer Stack" at 86.147,115.405 h1.52
  text "Top Overlay" at 9.713,112.357 h1.52
  text "Top Solder" at 9.713,109.309 h1.52
  text "Solder Resist" at 33.329,109.309 h1.52
  text "0,70mil" at 55.167,109.309 h1.52
  text "4.2" at 71.673,109.309 h1.52
  text "1" at -0.699,106.261 h1.52
  text "Top Layer" at 9.713,106.261 h1.52
  text "1,60mil" at 55.167,106.261 h1.52
  text "Dielectric 1" at 9.713,103.213 h1.52
  text "FR-4" at 33.329,103.213 h1.52
  text "3,00mil" at 55.167,103.213 h1.52
  text "3.7" at 71.673,103.213 h1.52
  text "2" at -0.699,100.165 h1.52
  text "Internal 1" at 9.713,100.165 h1.52
  text "1,20mil" at 55.167,100.165 h1.52
  text "Dielectric 3" at 9.713,97.117 h1.52
  text "50,00mil" at 55.167,97.117 h1.52
  text "4.5" at 71.673,97.117 h1.52
  text "3" at -0.699,94.069 h1.52
  text "Internal 2" at 9.713,94.069 h1.52
  text "1,20mil" at 55.167,94.069 h1.52
  text "Dielectric 2" at 9.713,91.021 h1.52
  text "3,00mil" at 55.167,91.021 h1.52
  text "3.7" at 71.673,91.021 h1.52
  text "4" at -0.699,87.973 h1.52
  text "Bottom Layer" at 9.713,87.973 h1.52
  text "1,60mil" at 55.167,87.973 h1.52
  text "Bottom Solder" at 9.713,84.925 h1.52
  text "Solder Resist" at 33.329,84.925 h1.52
  text "0,70mil" at 55.167,84.925 h1.52
  text "4.2" at 71.673,84.925 h1.52
  text "Bottom Overlay" at 9.713,81.877 h1.52
  text "Symbol" at -0.519,73.911 h2.16
  text "Count" at 7.943,73.911 h2.16
  text "Hole Size" at 16.721,73.911 h2.16
  text "Plated" at 32.27,73.911 h2.16
  text "Hole Type" at 39.698,73.911 h2.16
  text "Drill Layer Pair" at 50.513,73.911 h2.16
  text "Via/Pad" at 71.012,73.911 h2.16
  text "Pad Shape" at 79.873,73.911 h2.16
  text "Template" at 91.449,73.911 h2.16
  text "Description" at 105.871,73.911 h2.16
  text "596" at 7.943,70.183 h1.8
  text "11,81mil (0,30mm)" at 16.721,70.183 h1.8
  text "PTH" at 32.27,70.183 h1.8
  text "Round" at 39.698,70.183 h1.8
  text "Top Layer - Bottom Layer" at 50.513,70.183 h1.8
  text "Via" at 71.012,70.183 h1.8
  text "Rounded" at 79.873,70.183 h1.8
  text "(Mixed)" at 91.449,70.183 h1.8
  text "2" at 7.943,66.454 h1.8
  text "39,37mil (1,00mm)" at 16.721,66.454 h1.8
  text "NPTH" at 32.27,66.454 h1.8
  text "Round" at 39.698,66.454 h1.8
  text "Top Layer - Bottom Layer" at 50.513,66.454 h1.8
  text "Pad" at 71.012,66.454 h1.8
  text "Rounded" at 79.873,66.454 h1.8
  text "c0hn100m105p-1" at 91.449,66.454 h1.8
  text "598 Total" at 7.943,62.726 h1.8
